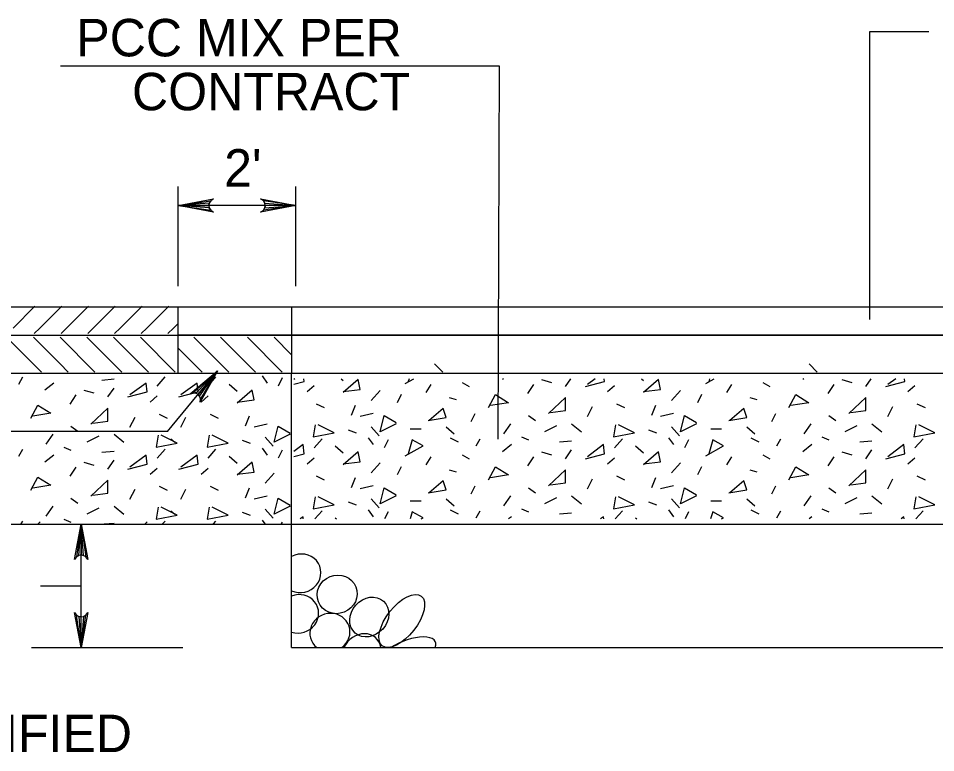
# Model space of a CAD drawing. Extents: x 3.47 to 10.73, y 1.11 to 10.92.
# Drawn here: x 5.858 to 7.328, y 8.502 to 9.679 of the extents above; entities that cross this region are included whole.
import ezdxf

# ---------------------------------------------------------------- set-up
doc = ezdxf.new("R2010")
doc.units = 0
for name, color, linetype in [('DETL-DIMS', 7, 'Continuous'), ('DETL-LINE', 7, 'Continuous'), ('DETL-NOTE', 7, 'Continuous'), ('DETL-PATT', 7, 'Continuous')]:
    doc.layers.add(name, color=color, linetype=linetype)

msp = doc.modelspace()

# ---------------------------------------------------------------- linework, layer by layer
at = {"layer": 'DETL-DIMS'}
for p, q in [((6.114, 9.2497), (6.114, 9.4093)), ((6.3026, 9.2497), (6.3026, 9.4093)), ((6.3026, 9.379), (6.114, 9.379)), ((6.0971, 9.0169), (6.1771, 9.1141)), ((6.0971, 9.0169), (5.4256, 9.0169)), ((5.9585, 8.6704), (5.9585, 8.8681)), ((5.8932, 8.7692), (5.9585, 8.7692)), ((5.8789, 8.6704), (6.1213, 8.6704))]:
    msp.add_line(p, q, dxfattribs=at)
for points in [[(7.3167, 9.6571), (7.2217, 9.6571), (7.2217, 9.1962)], [(5.9255, 9.6027), (6.6284, 9.6027), (6.6264, 9.0044)], [(6.114, 9.379), (6.1705, 9.3896), (6.1661, 9.3866), (6.1639, 9.3828), (6.1632, 9.379), (6.1639, 9.3752), (6.1661, 9.3714), (6.1705, 9.3684), (6.114, 9.379), (6.1661, 9.3714), (6.1639, 9.3752), (6.114, 9.379), (6.1632, 9.379), (6.1639, 9.3828), (6.114, 9.379), (6.1661, 9.3866)], [(6.3026, 9.379), (6.2461, 9.3684), (6.2505, 9.3714), (6.2527, 9.3752), (6.2534, 9.379), (6.2527, 9.3828), (6.2505, 9.3866), (6.2461, 9.3896), (6.3026, 9.379), (6.2505, 9.3866), (6.2527, 9.3828), (6.3026, 9.379), (6.2534, 9.379), (6.2527, 9.3752), (6.3026, 9.379), (6.2505, 9.3714)], [(6.1771, 9.1141), (6.1494, 9.0637), (6.1498, 9.069), (6.1483, 9.0732), (6.1458, 9.0761), (6.1424, 9.078), (6.1381, 9.0787), (6.133, 9.0772), (6.1771, 9.1141), (6.1381, 9.0787), (6.1424, 9.078), (6.1771, 9.1141), (6.1458, 9.0761), (6.1483, 9.0732), (6.1771, 9.1141), (6.1498, 9.069)], [(5.9585, 8.8681), (5.9691, 8.8116), (5.9661, 8.816), (5.9623, 8.8182), (5.9585, 8.8189), (5.9547, 8.8182), (5.9509, 8.816), (5.9479, 8.8116), (5.9585, 8.8681), (5.9509, 8.816), (5.9547, 8.8182), (5.9585, 8.8681), (5.9585, 8.8189), (5.9623, 8.8182), (5.9585, 8.8681), (5.9661, 8.816)], [(5.9585, 8.6704), (5.9479, 8.7268), (5.9509, 8.7225), (5.9547, 8.7202), (5.9585, 8.7196), (5.9623, 8.7202), (5.9661, 8.7225), (5.9691, 8.7268), (5.9585, 8.6704), (5.9661, 8.7225), (5.9623, 8.7202), (5.9585, 8.6704), (5.9585, 8.7196), (5.9547, 8.7202), (5.9585, 8.6704), (5.9509, 8.7225)]]:
    msp.add_lwpolyline(points, dxfattribs=at)
at = {"layer": 'DETL-LINE'}
for p, q in [((5.5382, 9.2166), (8.3867, 9.2166)), ((6.114, 9.1105), (6.114, 9.2166)), ((6.296, 9.1105), (6.296, 9.2166)), ((5.5382, 9.1711), (8.3867, 9.1711)), ((5.5382, 9.1105), (8.3867, 9.1105)), ((6.2958, 8.6704), (6.2958, 9.1105)), ((5.5382, 8.8681), (6.2958, 8.8681)), ((6.2958, 8.8681), (7.6291, 8.8681)), ((6.2958, 8.8681), (7.6291, 8.8681)), ((6.2958, 8.6704), (7.6291, 8.6704))]:
    msp.add_line(p, q, dxfattribs=at)
msp.add_lwpolyline([(6.114, 9.2166), (7.811, 9.2166), (7.811, 9.1711), (6.114, 9.1711)], close=True, dxfattribs=at)
at = {"layer": 'DETL-PATT'}
for p, q in [((5.8494, 9.1826), (5.8846, 9.2179)), ((5.8922, 9.1826), (5.9275, 9.2179)), ((5.9351, 9.1826), (5.9704, 9.2179)), ((5.978, 9.1826), (6.0132, 9.2179)), ((6.0208, 9.1826), (6.0561, 9.2179)), ((6.0637, 9.1826), (6.0989, 9.2179)), ((6.1065, 9.1826), (6.114, 9.1901)), ((5.8834, 9.1738), (5.8922, 9.1826)), ((5.9263, 9.1738), (5.9351, 9.1826)), ((5.9691, 9.1738), (5.978, 9.1826)), ((6.012, 9.1738), (6.0208, 9.1826)), ((6.0549, 9.1738), (6.0637, 9.1826)), ((6.0977, 9.1738), (6.1065, 9.1826)), ((5.895, 9.1121), (5.8392, 9.168)), ((5.9249, 9.1251), (5.8821, 9.168)), ((5.9807, 9.1121), (5.9249, 9.168)), ((6.0236, 9.1121), (5.9678, 9.168)), ((6.0664, 9.1121), (6.0106, 9.168)), ((6.1093, 9.1121), (6.0535, 9.168)), ((6.195, 9.1121), (6.1392, 9.168)), ((6.2379, 9.1121), (6.182, 9.168)), ((6.2807, 9.1121), (6.2249, 9.168)), ((6.2958, 9.1399), (6.2678, 9.168)), ((6.1522, 9.1121), (6.114, 9.1503)), ((5.9379, 9.1121), (5.9249, 9.1251)), ((6.5379, 9.1121), (6.5249, 9.1251)), ((7.1378, 9.1121), (7.1249, 9.1251)), ((5.8587, 9.0929), (5.8651, 9.1042)), ((5.9919, 9.0993), (6.0112, 9.101)), ((6.0802, 9.0897), (6.093, 9.1042)), ((6.1618, 9.0897), (6.1746, 9.1042)), ((6.2485, 9.1058), (6.2565, 9.0945)), ((6.2805, 9.1026), (6.2741, 9.0897)), ((6.3009, 9.1012), (6.2994, 9.1002)), ((6.375, 9.1012), (6.3783, 9.0983)), ((6.4778, 9.0935), (6.4917, 9.1012)), ((6.4839, 9.1012), (6.4826, 9.0967)), ((6.6351, 9.1012), (6.6334, 9.1)), ((6.696, 9.1), (6.7121, 9.0951)), ((6.7345, 9.0887), (6.7429, 9.1012)), ((6.7822, 9.1012), (6.7698, 9.0919)), ((6.8564, 9.1012), (6.8597, 9.0983)), ((6.9592, 9.0935), (6.973, 9.1012)), ((6.9653, 9.1012), (6.964, 9.0967)), ((7.1165, 9.1012), (7.1148, 9.1)), ((7.1774, 9.1), (7.1934, 9.0951)), ((7.2159, 9.0887), (7.2242, 9.1012)), ((7.2636, 9.1012), (7.2512, 9.0919)), ((5.9149, 9.0945), (5.9004, 9.0833)), ((5.963, 9.0833), (5.9791, 9.0785)), ((6.0015, 9.0721), (6.0112, 9.0865)), ((6.1955, 9.0929), (6.2083, 9.0817)), ((6.3205, 9.0807), (6.3318, 9.0903)), ((6.5115, 9.0791), (6.5195, 9.0919)), ((6.5692, 9.0951), (6.5805, 9.0887)), ((6.6832, 9.0919), (6.6735, 9.0775)), ((6.8019, 9.0807), (6.8131, 9.0903)), ((6.9929, 9.0791), (7.0009, 9.0919)), ((7.0506, 9.0951), (7.0619, 9.0887)), ((7.1645, 9.0919), (7.1549, 9.0775)), ((7.2833, 9.0807), (7.2945, 9.0903)), ((5.9502, 9.0753), (5.9406, 9.0608)), ((6.0689, 9.064), (6.0802, 9.0737)), ((6.1506, 9.064), (6.1618, 9.0737)), ((6.4377, 9.0823), (6.4232, 9.0663)), ((6.4714, 9.0759), (6.4649, 9.063)), ((6.5484, 9.0711), (6.5596, 9.0679)), ((6.919, 9.0823), (6.9046, 9.0663)), ((6.9527, 9.0759), (6.9463, 9.063)), ((7.0298, 9.0711), (7.041, 9.0679)), ((6.335, 9.0614), (6.3478, 9.055)), ((6.3976, 9.0582), (6.3911, 9.0422)), ((6.7698, 9.0406), (6.7778, 9.0566)), ((6.8163, 9.0614), (6.8292, 9.055)), ((6.8789, 9.0582), (6.8725, 9.0422)), ((7.2512, 9.0406), (7.2592, 9.0566)), ((7.2977, 9.0614), (7.3106, 9.055)), ((6.0368, 9.0239), (6.0449, 9.04)), ((6.0834, 9.0448), (6.0962, 9.0384)), ((6.1185, 9.0239), (6.1265, 9.04)), ((6.165, 9.0448), (6.1779, 9.0384)), ((6.2276, 9.0416), (6.2212, 9.0255)), ((6.4264, 9.0454), (6.4056, 9.0406)), ((6.5837, 9.0326), (6.5901, 9.0454)), ((6.6751, 9.0422), (6.6864, 9.0342)), ((6.9078, 9.0454), (6.887, 9.0406)), ((7.0651, 9.0326), (7.0715, 9.0454)), ((7.1565, 9.0422), (7.1678, 9.0342)), ((5.9422, 9.0255), (5.9534, 9.0175)), ((6.2565, 9.0287), (6.2356, 9.0239)), ((6.4232, 9.0245), (6.4361, 9.0101)), ((6.5436, 9.0245), (6.5564, 9.0133)), ((6.6463, 9.0293), (6.635, 9.0133)), ((6.7201, 9.0261), (6.7008, 9.0165)), ((6.7441, 9.0293), (6.7602, 9.0165)), ((6.9046, 9.0245), (6.9174, 9.0101)), ((7.0249, 9.0245), (7.0378, 9.0133)), ((7.1276, 9.0293), (7.1164, 9.0133)), ((7.2015, 9.0261), (7.1822, 9.0165)), ((7.2255, 9.0293), (7.2416, 9.0165)), ((5.9133, 9.0127), (5.902, 8.9967)), ((6.0112, 9.0127), (6.0272, 8.9999)), ((6.3863, 9.0197), (6.3992, 9.0149)), ((6.4858, 9.0213), (6.5035, 9.0213)), ((6.8677, 9.0197), (6.8805, 9.0149)), ((6.9672, 9.0213), (6.9848, 9.0213)), ((5.9871, 9.0095), (5.9678, 8.9999)), ((6.1023, 9.0051), (6.1089, 8.9999)), ((6.2164, 9.0031), (6.2292, 8.9983)), ((6.2533, 9.0079), (6.2661, 8.9934)), ((6.3318, 8.9908), (6.3446, 9.0053)), ((6.4184, 9.0069), (6.4264, 8.9957)), ((6.4505, 9.0037), (6.4441, 8.9908)), ((6.55, 9.0069), (6.5628, 9.0005)), ((6.5917, 8.994), (6.5981, 9.0053)), ((6.6479, 8.9957), (6.6334, 8.9844)), ((6.6639, 9.0085), (6.6751, 9.0037)), ((6.7249, 9.0005), (6.7441, 9.0021)), ((6.8131, 8.9908), (6.826, 9.0053)), ((6.8998, 9.0069), (6.9078, 8.9957)), ((6.9319, 9.0037), (6.9255, 8.9908)), ((7.0314, 9.0069), (7.0442, 9.0005)), ((7.0731, 8.994), (7.0795, 9.0053)), ((7.1292, 8.9957), (7.1148, 8.9844)), ((7.1453, 9.0085), (7.1565, 9.0037)), ((7.2063, 9.0005), (7.2255, 9.0021)), ((7.2945, 8.9908), (7.3074, 9.0053)), ((5.8587, 8.9774), (5.8651, 8.9886)), ((5.9309, 8.9918), (5.9422, 8.987)), ((5.9919, 8.9838), (6.0112, 8.9854)), ((6.0802, 8.9742), (6.093, 8.9886)), ((6.1618, 8.9742), (6.1746, 8.9886)), ((6.2485, 8.9902), (6.2565, 8.979)), ((6.2805, 8.987), (6.2741, 8.9742)), ((6.3655, 8.994), (6.3783, 8.9828)), ((6.696, 8.9844), (6.7121, 8.9796)), ((6.7345, 8.9732), (6.7441, 8.9876)), ((6.8468, 8.994), (6.8597, 8.9828)), ((7.1774, 8.9844), (7.1934, 8.9796)), ((7.2159, 8.9732), (7.2255, 8.9876)), ((5.9149, 8.979), (5.9004, 8.9678)), ((5.963, 8.9678), (5.9791, 8.963)), ((6.0015, 8.9565), (6.0112, 8.971)), ((6.1955, 8.9774), (6.2083, 8.9662)), ((6.3205, 8.9652), (6.3318, 8.9748)), ((6.4377, 8.9668), (6.4232, 8.9507)), ((6.5115, 8.9636), (6.5195, 8.9764)), ((6.5692, 8.9796), (6.5805, 8.9732)), ((6.6832, 8.9764), (6.6735, 8.962)), ((6.8019, 8.9652), (6.8131, 8.9748)), ((6.919, 8.9668), (6.9046, 8.9507)), ((6.9929, 8.9636), (7.0009, 8.9764)), ((7.0506, 8.9796), (7.0619, 8.9732)), ((7.1645, 8.9764), (7.1549, 8.962)), ((7.2833, 8.9652), (7.2945, 8.9748)), ((5.9502, 8.9597), (5.9406, 8.9453)), ((6.0689, 8.9485), (6.0802, 8.9581)), ((6.1506, 8.9485), (6.1618, 8.9581)), ((6.4714, 8.9604), (6.4649, 8.9475)), ((6.5484, 8.9555), (6.5596, 8.9523)), ((6.9527, 8.9604), (6.9463, 8.9475)), ((7.0298, 8.9555), (7.041, 8.9523)), ((6.2677, 8.9501), (6.2533, 8.9341)), ((6.335, 8.9459), (6.3478, 8.9395)), ((6.3976, 8.9427), (6.3911, 8.9267)), ((6.7698, 8.9251), (6.7778, 8.9411)), ((6.8163, 8.9459), (6.8292, 8.9395)), ((6.8789, 8.9427), (6.8725, 8.9267)), ((7.2512, 8.9251), (7.2592, 8.9411)), ((7.2977, 8.9459), (7.3106, 8.9395)), ((6.0368, 8.9084), (6.0449, 8.9244)), ((6.0834, 8.9293), (6.0962, 8.9228)), ((6.1185, 8.9084), (6.1265, 8.9244)), ((6.165, 8.9293), (6.1779, 8.9228)), ((6.2276, 8.926), (6.2212, 8.91)), ((6.4264, 8.9299), (6.4056, 8.9251)), ((6.5837, 8.917), (6.5901, 8.9299)), ((6.6751, 8.9267), (6.6864, 8.9186)), ((6.9078, 8.9299), (6.887, 8.9251)), ((7.0651, 8.917), (7.0715, 8.9299)), ((7.1565, 8.9267), (7.1678, 8.9186)), ((5.9422, 8.91), (5.9534, 8.902)), ((6.2565, 8.9132), (6.2356, 8.9084)), ((6.4232, 8.909), (6.4361, 8.8946)), ((6.5436, 8.909), (6.5564, 8.8978)), ((6.6463, 8.9138), (6.635, 8.8978)), ((6.7201, 8.9106), (6.7008, 8.901)), ((6.7441, 8.9138), (6.7602, 8.901)), ((6.9046, 8.909), (6.9174, 8.8946)), ((7.0249, 8.909), (7.0378, 8.8978)), ((7.1276, 8.9138), (7.1164, 8.8978)), ((7.2015, 8.9106), (7.1822, 8.901)), ((7.2255, 8.9138), (7.2416, 8.901)), ((5.9133, 8.8972), (5.902, 8.8811)), ((5.9871, 8.894), (5.9678, 8.8843)), ((6.0112, 8.8972), (6.0272, 8.8843)), ((6.2533, 8.8924), (6.2661, 8.8779)), ((6.3863, 8.9042), (6.3992, 8.8994)), ((6.4858, 8.9058), (6.5035, 8.9058)), ((6.6639, 8.893), (6.6751, 8.8881)), ((6.8677, 8.9042), (6.8805, 8.8994)), ((6.9672, 8.9058), (6.9848, 8.9058)), ((7.1453, 8.893), (7.1565, 8.8881)), ((6.1023, 8.8896), (6.1089, 8.8843)), ((6.2164, 8.8875), (6.2292, 8.8827)), ((6.333, 8.8767), (6.3446, 8.8897)), ((6.3655, 8.8785), (6.3676, 8.8767)), ((6.4184, 8.8914), (6.4264, 8.8801)), ((6.4505, 8.8881), (6.4448, 8.8767)), ((6.55, 8.8914), (6.5628, 8.8849)), ((6.5917, 8.8785), (6.5981, 8.8897)), ((6.6479, 8.8801), (6.6434, 8.8767)), ((6.7249, 8.8849), (6.7441, 8.8865)), ((6.8144, 8.8767), (6.826, 8.8897)), ((6.8468, 8.8785), (6.8489, 8.8767)), ((6.8998, 8.8914), (6.9078, 8.8801)), ((6.9319, 8.8881), (6.9261, 8.8767)), ((7.0314, 8.8914), (7.0442, 8.8849)), ((7.0731, 8.8785), (7.0795, 8.8897)), ((7.1292, 8.8801), (7.1248, 8.8767)), ((7.2063, 8.8849), (7.2255, 8.8865)), ((7.2957, 8.8767), (7.3074, 8.8897)), ((5.8626, 8.8686), (5.8651, 8.8731)), ((5.8892, 8.8681), (5.8931, 8.872)), ((5.9309, 8.8763), (5.9422, 8.8715)), ((5.9955, 8.8686), (6.0112, 8.8699)), ((6.0606, 8.8681), (6.0645, 8.872)), ((6.089, 8.8686), (6.093, 8.8731)), ((6.1706, 8.8686), (6.1746, 8.8731)), ((6.2485, 8.8747), (6.2528, 8.8686)), ((6.2805, 8.8715), (6.2791, 8.8686))]:
    msp.add_line(p, q, dxfattribs=at)
for points in [[(6.2994, 9.0925), (6.3157, 9.0967), (6.3152, 9.1012)], [(6.3783, 9.0807), (6.4056, 9.0839), (6.4024, 9.1), (6.3783, 9.0791)], [(6.7666, 9.0887), (6.7971, 9.0967), (6.7966, 9.1012)], [(6.8597, 9.0807), (6.887, 9.0839), (6.8837, 9.1), (6.8597, 9.0791)], [(7.248, 9.0887), (7.2785, 9.0967), (7.278, 9.1012)], [(6.0336, 9.0721), (6.0641, 9.0801), (6.0625, 9.0945), (6.0368, 9.0753)], [(6.1153, 9.0721), (6.1458, 9.0801), (6.1442, 9.0945), (6.1185, 9.0753)], [(6.2083, 9.064), (6.2356, 9.0673), (6.2324, 9.0833), (6.2083, 9.0624)], [(6.611, 9.055), (6.6222, 9.0759), (6.6431, 9.063), (6.6142, 9.0582)], [(6.7104, 9.047), (6.7345, 9.0502), (6.7345, 9.0711), (6.7072, 9.0454)], [(7.0923, 9.055), (7.1036, 9.0759), (7.1244, 9.063), (7.0955, 9.0582)], [(7.1918, 9.047), (7.2159, 9.0502), (7.2159, 9.0711), (7.1886, 9.0454)], [(5.878, 9.0384), (5.8892, 9.0592), (5.9101, 9.0464), (5.8812, 9.0416)], [(5.9775, 9.0303), (6.0015, 9.0336), (6.0015, 9.0544), (5.9743, 9.0287)], [(6.4633, 9.0293), (6.4377, 9.0165), (6.4441, 9.0422), (6.4633, 9.031)], [(6.5147, 9.0342), (6.5436, 9.039), (6.5388, 9.0534), (6.5163, 9.0342)], [(6.9447, 9.0293), (6.919, 9.0165), (6.9255, 9.0422), (6.9447, 9.031)], [(6.9961, 9.0342), (7.0249, 9.039), (7.0201, 9.0534), (6.9977, 9.0342)], [(6.2934, 9.0127), (6.2677, 8.9999), (6.2741, 9.0255), (6.2934, 9.0143)], [(6.3334, 9.0277), (6.3302, 9.0085), (6.3639, 9.0149), (6.3382, 9.0277)], [(6.8147, 9.0277), (6.8115, 9.0085), (6.8452, 9.0149), (6.8196, 9.0277)], [(7.2961, 9.0277), (7.2929, 9.0085), (7.3266, 9.0149), (7.3009, 9.0277)], [(6.0818, 9.0111), (6.0786, 8.9918), (6.1122, 8.9983), (6.0866, 9.0111)], [(6.1634, 9.0111), (6.1602, 8.9918), (6.1939, 8.9983), (6.1682, 9.0111)], [(6.2994, 8.9769), (6.3157, 8.9812), (6.3141, 8.9957), (6.2994, 8.9846)], [(6.4778, 8.978), (6.5067, 8.994), (6.489, 9.0037), (6.4826, 8.9812)], [(6.7666, 8.9732), (6.7971, 8.9812), (6.7955, 8.9957), (6.7698, 8.9764)], [(6.9592, 8.978), (6.988, 8.994), (6.9704, 9.0037), (6.964, 8.9812)], [(7.248, 8.9732), (7.2785, 8.9812), (7.2769, 8.9957), (7.2512, 8.9764)], [(6.3783, 8.9652), (6.4056, 8.9684), (6.4024, 8.9844), (6.3783, 8.9636)], [(6.8597, 8.9652), (6.887, 8.9684), (6.8837, 8.9844), (6.8597, 8.9636)], [(6.0336, 8.9565), (6.0641, 8.9646), (6.0625, 8.979), (6.0368, 8.9597)], [(6.1153, 8.9565), (6.1458, 8.9646), (6.1442, 8.979), (6.1185, 8.9597)], [(6.2083, 8.9485), (6.2356, 8.9517), (6.2324, 8.9678), (6.2083, 8.9469)], [(6.611, 8.9395), (6.6222, 8.9604), (6.6431, 8.9475), (6.6142, 8.9427)], [(6.7104, 8.9315), (6.7345, 8.9347), (6.7345, 8.9555), (6.7072, 8.9299)], [(7.0923, 8.9395), (7.1036, 8.9604), (7.1244, 8.9475), (7.0955, 8.9427)], [(7.1918, 8.9315), (7.2159, 8.9347), (7.2159, 8.9555), (7.1886, 8.9299)], [(5.878, 8.9228), (5.8892, 8.9437), (5.9101, 8.9309), (5.8812, 8.926)], [(5.9775, 8.9148), (6.0015, 8.918), (6.0015, 8.9389), (5.9743, 8.9132)], [(6.5147, 8.9186), (6.5436, 8.9234), (6.5388, 8.9379), (6.5163, 8.9186)], [(6.9961, 8.9186), (7.0249, 8.9234), (7.0201, 8.9379), (6.9977, 8.9186)], [(6.4633, 8.9138), (6.4377, 8.901), (6.4441, 8.9267), (6.4633, 8.9154)], [(6.9447, 8.9138), (6.919, 8.901), (6.9255, 8.9267), (6.9447, 8.9154)], [(6.2934, 8.8972), (6.2677, 8.8843), (6.2741, 8.91), (6.2934, 8.8988)], [(6.3334, 8.9122), (6.3302, 8.893), (6.3639, 8.8994), (6.3382, 8.9122)], [(6.8147, 8.9122), (6.8115, 8.893), (6.8452, 8.8994), (6.8196, 8.9122)], [(7.2961, 8.9122), (7.2929, 8.893), (7.3266, 8.8994), (7.3009, 8.9122)], [(6.0818, 8.8956), (6.0786, 8.8763), (6.1122, 8.8827), (6.0866, 8.8956)], [(6.1634, 8.8956), (6.1602, 8.8763), (6.1939, 8.8827), (6.1682, 8.8956)], [(6.3145, 8.8767), (6.3141, 8.8801), (6.3095, 8.8767)], [(6.5034, 8.8767), (6.5067, 8.8785), (6.489, 8.8881), (6.4857, 8.8767)], [(6.7959, 8.8767), (6.7955, 8.8801), (6.7909, 8.8767)], [(6.9847, 8.8767), (6.988, 8.8785), (6.9704, 8.8881), (6.9671, 8.8767)], [(7.2772, 8.8767), (7.2769, 8.8801), (7.2723, 8.8767)]]:
    msp.add_lwpolyline(points, dxfattribs=at)
for centre, major_axis, ratio, start_param, end_param in [((6.3106, 8.7895), (0.03, 0.012), 0.948581, 3.86971, 7.971447), ((6.307, 8.7245), (0.03, 0.012), 0.948581, 3.994159, 7.846998), ((6.3571, 8.6944), (0.03, 0.012), 0.948581, 4.992896, 9.917049), ((6.4075, 8.6608), (0.0227, 0.0256), 0.844245, 5.660134, 8.193891), ((6.48, 8.6598), (-0.0464, -0.0197), 0.422273, 2.743765, 5.105587)]:
    msp.add_ellipse(centre, major_axis=major_axis, ratio=ratio, start_param=start_param, end_param=end_param, dxfattribs=at)
for centre, major_axis, ratio in [((6.3687, 8.7557), (0.03, 0.012), 0.948581), ((6.4723, 8.7132), (-0.0313, -0.0398), 0.479042), ((6.4202, 8.7194), (0.0227, 0.0256), 0.844245)]:
    msp.add_ellipse(centre, major_axis=major_axis, ratio=ratio, dxfattribs=at)

# ---------------------------------------------------------------- texts
at = {"layer": 'DETL-NOTE'}
for s, p in [('PCC MIX PER', (5.9508, 9.618)), ('CONTRACT', (6.04, 9.5316)), ("2'", (6.1876, 9.4093)), ('OR AS SPECIFIED', (5.3445, 8.5029))]:
    msp.add_text(s, height=0.06, dxfattribs=at).set_placement(p)

doc.saveas('drawing.dxf')
